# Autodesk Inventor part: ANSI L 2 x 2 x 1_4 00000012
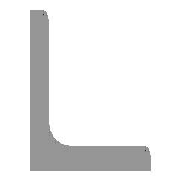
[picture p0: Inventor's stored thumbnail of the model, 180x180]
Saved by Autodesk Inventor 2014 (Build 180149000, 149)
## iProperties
IsCustomPart: 1
Created: 2007-02
Part Number: ANSI L 2 x 2 x 1_4 00000012
Material: Steel, Mild
Document SubType Name: Modeling
Standard: AISC
Designer: Autodesk, Inc.
Size Designation: L 2 x 2 x 1/4
Stock Number: L 2 x 2 x 1/4
Density: 7.86 g/cm^3
Description: Angle Steel
Standards Organization: ANSI
Language: en-US
Categories: <MemberInstance><Categories><Category DisplayName="Structural Shapes" InternalName="089c4875-fa83-4c05-b084-43b9cc11f5ed" Mnemonic="GRDR"><CategoryParameter Dis
Mass: 4984.2 g
Surface Area: 2071.11 cm^2
Volume: 634.122 cm^3
Appearance: Steel
_FrameMemberDoc: Frame Member File
_Version: 13.0.0
_CCFamilyMember: 11
_CCFamilyDisplayName: ANSI L (Equal angles) - Angle Steel
G_L: 41.250 in
G_W: 2.000 in
G_H: 2.000 in
+66D5F651-6C73-4E54-BC92-21E4DA75EC9E+CUTDETAIL1: Notch
+CF352427-B6DD-4A7B-8774-4A21CA8D84D1+CUTDETAIL2: Cut
+AB975018-38CB-4017-B372-74A5C2C524EF+CUTDETAIL3: Notch
Author: Autodesk, Inc.
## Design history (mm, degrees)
node "Start plane"
node "End plane"
sketch "Sketch"
  geometry: L1 (50.8, 0)-(0, 0); L2 (0, 0)-(0, 50.8); L3 (0, 50.8)-(3.302, 50.8); L4 (6.35, 47.752)-(6.35, 12.7); L5 (12.7, 6.35)-(47.752, 6.35); L6 (50.8, 3.302)-(50.8, 0); L7 (0, -11.041)-(0, 31.538); L8 (-11.041, 0)-(31.538, 0); L9 (0, 63.926)-(0, -23.536) reference; L10 (-23.536, 0)-(63.926, 0) reference; A1 r 6.35 centre (12.7, 12.7) between (6.35, 12.7) and (12.7, 6.35); A2 r 3.048 centre (3.302, 47.752) between (6.35, 47.752) and (3.302, 50.8); A3 r 3.048 centre (47.752, 3.302) between (50.8, 3.302) and (47.752, 6.35); 3 further points
  constraints: 16 end point, 6 point on circle, 6 point on line, 6 tangent, 4 parallel, 3 centre point, 2 collinear, 1 equal radius, 1 horizontal, 1 perpendicular
  dimensions: "d0" = 50.8 distance between parallel lines of L6 L2 (= G_H); "d1" = 50.8 distance between parallel lines of L3 L1 (= G_H); "d2" = 6.35 distance between parallel lines of L2 L4 (= G_T); "d3" = 6.35 distance between parallel lines of L1 L5 (= G_T); "d10" = 0 distance between parallel lines of L7 L2 (computed from ex); "d11" = 0 distance between parallel lines of L8 L1 (computed from d10); "d14" = 6.35 radius of A1 (= G_IR); "d15" = 3.048 radius of A2 (= G_ER)
extrude "Body" new body sketch "Sketch" stored distance "d4" = 1047.75 (= G_L); taper "d5" = 0 deg
node "Driven Length"
  sketch "Sketch5"
    geometry: L1 (0, 0)-(10, 0) reference
    constraints: 2 end point, 1 horizontal
  workplane "Work Plane8"
  sketch "Sketch6"
    geometry: L1 (-2, 0)-(12, 0) reference; L2 (-2, 1047.75)-(12, 1047.75) reference
    dimensions: "d21" = 1047.75 distance between parallel lines of L1 L2 (derived)
workplane "Work Plane3"
workplane "Work Plane4"
derived "ANSI L 2 x 2 x 1_4 00000006.ipt"
  sketch "Sketch_1"
    geometry: L1 (50.8, 0)-(0, 0) reference; L2 (0, 0)-(0, 50.8) reference; L3 (0, 50.8)-(3.302, 50.8) reference; L4 (6.35, 47.752)-(6.35, 12.7) reference; L5 (12.7, 6.35)-(47.752, 6.35) reference; L6 (50.8, 3.302)-(50.8, 0) reference; L7 (0, -11.041)-(0, 31.538) reference; L8 (-11.041, 0)-(31.538, 0) reference; L9 (0, 63.926)-(0, -23.536) reference; L10 (-23.536, 0)-(63.926, 0) reference; A1 r 6.35 centre (12.7, 12.7) between (6.35, 12.7) and (12.7, 6.35) reference; A2 r 3.048 centre (3.302, 47.752) between (6.35, 47.752) and (3.302, 50.8) reference; A3 r 3.048 centre (47.752, 3.302) between (50.8, 3.302) and (47.752, 6.35) reference; 3 further points
extrude "Extrusion2" cut sketch "Sketch_1" stored distance "d16" = 3.302; taper "d17" = 0 deg
workplane "Work Plane5"
split "Split1"
workplane "Work Plane6"
workplane "Work Plane7"
derived "ANSI L 2 x 2 x 1_4 00000007.ipt"
  sketch "Sketch_2"
    geometry: L1 (50.8, 0)-(0, 0) reference; L2 (0, 0)-(0, 50.8) reference; L3 (0, 50.8)-(3.302, 50.8) reference; L4 (6.35, 47.752)-(6.35, 12.7) reference; L5 (12.7, 6.35)-(47.752, 6.35) reference; L6 (50.8, 3.302)-(50.8, 0) reference; L7 (0, -11.041)-(0, 31.538) reference; L8 (-11.041, 0)-(31.538, 0) reference; L9 (0, 63.926)-(0, -23.536) reference; L10 (-23.536, 0)-(63.926, 0) reference; A1 r 6.35 centre (12.7, 12.7) between (6.35, 12.7) and (12.7, 6.35) reference; A2 r 3.048 centre (3.302, 47.752) between (6.35, 47.752) and (3.302, 50.8) reference; A3 r 3.048 centre (47.752, 3.302) between (50.8, 3.302) and (47.752, 6.35) reference; 3 further points
extrude "Extrusion3" cut sketch "Sketch_2" stored distance "d18" = 3.302; taper "d19" = 0 deg
body "Solid1"
other parameters: "G_H" = 50.8 [user parameter; used in 2 equation terms], "G_T" = 6.35 [user parameter; used in 2 equation terms], "G_ER" = 3.048 [user parameter; used in 1 equation term], "G_IR" = 6.35 [user parameter; used in 1 equation term], "G_L" = 1047.75 (= d21) [user parameter; used in 1 equation term], "ex" = 0 [user parameter; used in 1 equation term], "G_OFFSET_START" = 0 [user parameter; used in 1 equation term], "G_OFFSET_END" = -6.35 [user parameter; used in 1 equation term], "d12" = 0 (computed from G_OFFSET_START), "d13" = 1047.75 (= G_OFFSET_END + B_L), "B_L" = 1054.1 [user parameter; used in 1 equation term], "d20" = 90 deg
